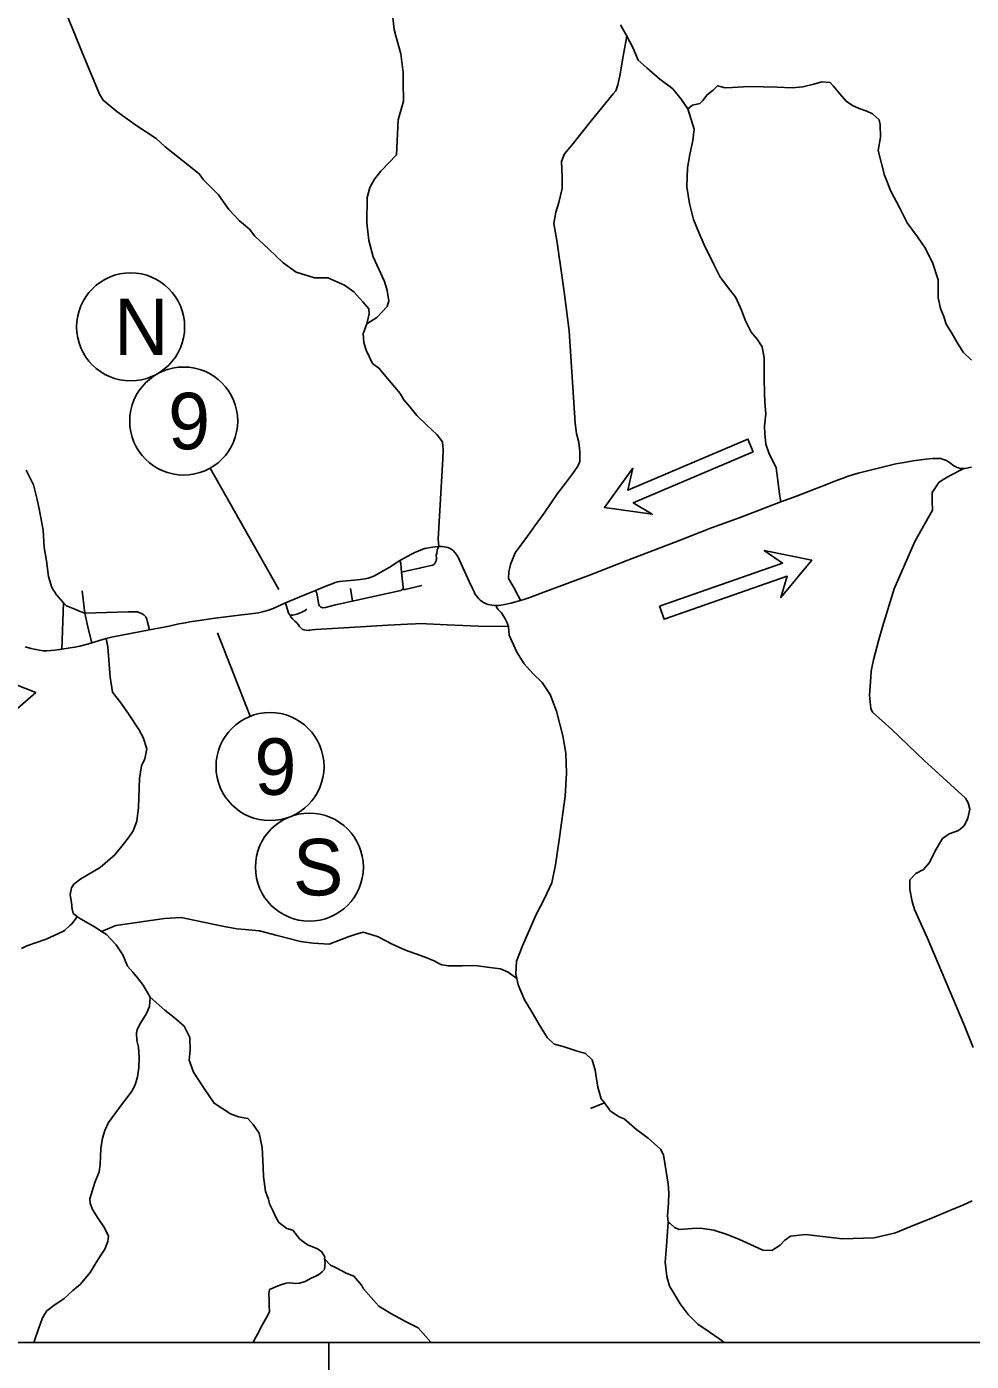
# Model space of a CAD drawing. Extents: x 2025369 to 2161369, y 549489 to 637489.
# Drawn here: x 2069680 to 2081050, y 571334 to 587393 of the extents above; entities that cross this region are included whole.
import ezdxf

# ---------------------------------------------------------------- set-up
doc = ezdxf.new("R2010")
doc.units = 0
for name, color, linetype in [('GM_X_County_Road', 7, 'Continuous'), ('GM_X_State_Route', 7, 'Continuous'), ('GM_X_Township_Road', 7, 'Continuous'), ('GM_X_Township_Subdivision', 7, 'Continuous'), ('SH_Text', 7, 'Continuous')]:
    doc.layers.add(name, color=color, linetype=linetype)

msp = doc.modelspace()

# ---------------------------------------------------------------- linework, layer by layer
at = {"layer": 'GM_X_County_Road'}
for points in [[(2074211, 586792), (2074210, 586841), (2074183, 587067), (2074128, 587266), (2074102, 587360), (2074085, 587539)], [(2078759, 581674), (2078741, 581768), (2078720, 581933), (2078703, 582084), (2078613, 582264), (2078576, 582370), (2078564, 582499), (2078561, 582585), (2078577, 582735), (2078566, 582873), (2078559, 582986), (2078555, 583154), (2078557, 583408), (2078533, 583541), (2078471, 583633), (2078402, 583716), (2078330, 583852), (2078283, 583981), (2078216, 584135), (2078116, 584262), (2078021, 584389), (2077951, 584531), (2077834, 584770), (2077769, 584915), (2077706, 585073), (2077658, 585266), (2077627, 585466), (2077632, 585693), (2077661, 585855), (2077698, 586023), (2077713, 586161), (2077636, 586406), (2077556, 586521), (2077457, 586646), (2077301, 586760), (2077146, 586897), (2077040, 586992), (2076977, 587142), (2076905, 587280), (2076826, 587416)], [(2073755, 583767), (2073775, 583816), (2073893, 583895), (2074020, 584027), (2074040, 584094), (2074020, 584217), (2073988, 584326), (2073850, 584625), (2073797, 584820), (2073775, 585034), (2073779, 585338), (2073811, 585460), (2073865, 585560), (2073942, 585655), (2074133, 585850), (2074151, 586274), (2074214, 586496), (2074211, 586731), (2074211, 586792)], [(2074296, 582814), (2074268, 582848), (2074218, 582904), (2074174, 582979), (2073919, 583286), (2073843, 583342), (2073765, 583500), (2073738, 583591), (2073728, 583700), (2073746, 583743), (2073755, 583767)], [(2074640, 581137), (2074634, 581227), (2074689, 582195), (2074692, 582301), (2074686, 582397), (2074616, 582484), (2074495, 582599), (2074377, 582715), (2074311, 582796), (2074296, 582814)], [(2078074, 571561), (2078025, 571602), (2077895, 571689), (2077760, 571779), (2077640, 571896), (2077547, 572025), (2077456, 572175), (2077418, 572238), (2077384, 572356), (2077365, 572526), (2077382, 572721), (2077401, 573009), (2077393, 573085), (2077404, 573242), (2077411, 573358), (2077401, 573466), (2077378, 573617), (2077345, 573819), (2077309, 573885), (2077162, 574020), (2077024, 574119), (2076870, 574252), (2076813, 574276), (2076709, 574345), (2076635, 574442), (2076595, 574494), (2076556, 574634), (2076540, 574734), (2076523, 574839), (2076487, 574963), (2076408, 575037), (2076292, 575070), (2076138, 575121), (2076028, 575149), (2075944, 575230), (2075849, 575388), (2075748, 575559), (2075672, 575682), (2075597, 575864), (2075578, 575942), (2075566, 575991), (2075576, 576147), (2075649, 576335), (2075716, 576489), (2075817, 576719), (2075914, 576901), (2076001, 577093), (2076044, 577308), (2076095, 577636), (2076162, 578133), (2076177, 578409), (2076168, 578650), (2076135, 578862), (2076058, 579157), (2075979, 579356), (2075886, 579503), (2075774, 579611), (2075669, 579726), (2075581, 579867), (2075488, 580072), (2075478, 580175), (2075461, 580228), (2075436, 580277), (2075397, 580340), (2075374, 580360), (2075355, 580379), (2075340, 580400), (2075329, 580427)], [(2069766, 571561), (2069782, 571610), (2069838, 571770), (2069874, 571866), (2069923, 571943), (2070005, 572005), (2070130, 572091), (2070237, 572185), (2070326, 572262), (2070444, 572404), (2070504, 572502), (2070566, 572600), (2070619, 572685), (2070657, 572776), (2070666, 572840), (2070615, 572938), (2070540, 573052), (2070471, 573162), (2070446, 573236), (2070441, 573290), (2070501, 573486), (2070553, 573615), (2070565, 573701), (2070571, 573895), (2070591, 574017), (2070620, 574110), (2070665, 574209), (2070752, 574328), (2070822, 574419), (2070890, 574509), (2070944, 574583), (2070984, 574662), (2071013, 574757), (2071029, 574864), (2071035, 574990), (2071024, 575115), (2071006, 575194), (2071000, 575282), (2071008, 575326), (2071049, 575401), (2071124, 575517), (2071158, 575603), (2071165, 575717), (2071081, 575859), (2071014, 575948), (2070957, 576015), (2070895, 576088), (2070837, 576226), (2070758, 576345), (2070642, 576469), (2070581, 576507), (2070516, 576548), (2070391, 576621), (2070308, 576670), (2070289, 576685), (2070240, 576723), (2070227, 576773), (2070218, 576851), (2070205, 576950), (2070220, 577031), (2070248, 577077), (2070331, 577138), (2070448, 577208), (2070565, 577277), (2070741, 577427), (2070842, 577551), (2070901, 577627), (2070962, 577716), (2071007, 577833), (2071025, 577997), (2071039, 578345), (2071063, 578500), (2071100, 578584), (2071125, 578703), (2071083, 578838), (2071030, 578936), (2070912, 579112), (2070815, 579257), (2070754, 579334), (2070711, 579386), (2070683, 579566), (2070656, 579930), (2070635, 580030)]]:
    msp.add_lwpolyline(points, dxfattribs=at)
at = {"layer": 'GM_X_State_Route'}
for points in [[(2075329, 580427), (2075359, 580429), (2075391, 580434), (2075435, 580442), (2075508, 580457), (2075625, 580489), (2075677, 580504), (2075735, 580523), (2075871, 580575), (2076465, 580799), (2076914, 580972), (2077525, 581205), (2077923, 581361), (2078266, 581489), (2078759, 581674), (2078945, 581745), (2079307, 581884), (2079427, 581931), (2079506, 581960), (2079557, 581979), (2079618, 581999), (2079687, 582019), (2079799, 582050), (2080012, 582102), (2080140, 582131), (2080241, 582151), (2080348, 582169), (2080413, 582178), (2080501, 582189), (2080582, 582197), (2080632, 582199), (2080663, 582198), (2080683, 582196), (2080705, 582191), (2080729, 582182), (2080750, 582172), (2080788, 582149), (2080841, 582110), (2080862, 582097), (2080879, 582089), (2080895, 582083), (2080915, 582077), (2080932, 582075), (2080946, 582075), (2080960, 582075), (2080977, 582078), (2080997, 582082), (2081029, 582088), (2081053, 582091)], [(2069661, 579932), (2069732, 579912), (2069768, 579903), (2069793, 579897), (2069831, 579889), (2069882, 579884), (2069923, 579883), (2069971, 579885), (2070018, 579889), (2070102, 579901), (2070202, 579917), (2070261, 579926), (2070320, 579938), (2070396, 579958), (2070463, 579978), (2070635, 580030), (2070683, 580042), (2070722, 580051), (2071158, 580134), (2071394, 580181), (2071513, 580206), (2071592, 580221), (2071644, 580231), (2071705, 580241), (2071790, 580253), (2071918, 580271), (2072271, 580315), (2072340, 580323), (2072406, 580332), (2072470, 580342), (2072535, 580356), (2072590, 580371), (2072647, 580391), (2072794, 580462), (2073077, 580577), (2073158, 580609), (2073222, 580635), (2073311, 580672), (2073358, 580690), (2073393, 580704), (2073422, 580712), (2073449, 580718), (2073486, 580723), (2073623, 580734), (2073692, 580740), (2073721, 580744), (2073754, 580750), (2073789, 580757), (2073828, 580770), (2073865, 580786), (2073942, 580828), (2074041, 580886), (2074173, 580971), (2074267, 581023), (2074304, 581043), (2074361, 581071), (2074390, 581083), (2074421, 581096), (2074449, 581107), (2074474, 581113), (2074498, 581119), (2074541, 581128), (2074595, 581133), (2074640, 581137)], [(2074640, 581137), (2074680, 581137), (2074704, 581135), (2074727, 581132), (2074748, 581127), (2074768, 581119), (2074790, 581107), (2074812, 581092), (2074835, 581068), (2074849, 581048), (2074873, 581008), (2074926, 580893), (2075005, 580716), (2075046, 580631), (2075065, 580593), (2075076, 580570), (2075089, 580549), (2075102, 580531), (2075121, 580510), (2075139, 580493), (2075166, 580473), (2075187, 580461), (2075211, 580450), (2075235, 580441), (2075279, 580431), (2075305, 580427), (2075329, 580427)]]:
    msp.add_lwpolyline(points, dxfattribs=at)
at = {"layer": 'GM_X_Township_Road'}
for points in [[(2073775, 583816), (2073801, 583938), (2073798, 583998), (2073727, 584084), (2073616, 584204), (2073507, 584281), (2073306, 584371), (2073145, 584373), (2072922, 584440), (2072767, 584550), (2072591, 584720), (2072427, 584874), (2072361, 584957), (2072243, 585058), (2072112, 585194), (2071988, 585371), (2071810, 585549), (2071757, 585624), (2071501, 585829), (2071346, 585949), (2071237, 586046), (2070993, 586209), (2070766, 586371), (2070602, 586507), (2070556, 586582), (2070338, 587102), (2070256, 587313), (2070171, 587514)], [(2076094, 584593), (2076066, 584795), (2076025, 585026), (2076051, 585160), (2076086, 585278), (2076127, 585444), (2076127, 585588), (2076116, 585771), (2076152, 585863), (2076243, 585967), (2076476, 586259), (2076738, 586584), (2076770, 586622), (2076796, 586694), (2076819, 586800), (2076860, 587037), (2076905, 587280)], [(2081052, 583381), (2080952, 583475), (2080878, 583592), (2080817, 583706), (2080749, 583815), (2080718, 583905), (2080680, 584001), (2080651, 584132), (2080650, 584348), (2080581, 584557), (2080491, 584738), (2080404, 584866), (2080279, 585033), (2080185, 585218), (2080080, 585413), (2080005, 585605), (2079930, 585902), (2079957, 586065), (2079952, 586217), (2079940, 586271), (2079860, 586343), (2079792, 586376), (2079701, 586408), (2079621, 586443), (2079545, 586497), (2079469, 586586), (2079388, 586682), (2079350, 586720), (2079252, 586731), (2079154, 586703), (2079023, 586669), (2078893, 586658), (2078713, 586665), (2078375, 586674), (2078175, 586661), (2078087, 586657), (2077995, 586683), (2077941, 586628), (2077872, 586572), (2077818, 586504), (2077784, 586470), (2077692, 586450), (2077636, 586406)], [(2075843, 581450), (2075917, 581553), (2076070, 581777), (2076165, 581901), (2076249, 582013), (2076314, 582105), (2076336, 582163), (2076338, 582281), (2076327, 582391), (2076299, 582497), (2076282, 582624), (2076209, 583732), (2076149, 584204), (2076097, 584573), (2076094, 584593)], [(2070325, 580357), (2070260, 580383), (2070158, 580423), (2070124, 580461), (2070038, 580555), (2069981, 580646), (2069941, 580778), (2069920, 580967), (2069892, 581127), (2069878, 581335), (2069831, 581590), (2069803, 581720), (2069762, 581880), (2069672, 582057)], [(2081072, 575109), (2080958, 575390), (2080518, 576432), (2080367, 576770), (2080340, 576868), (2080309, 577012), (2080309, 577127), (2080381, 577204), (2080476, 577252), (2080546, 577336), (2080613, 577478), (2080703, 577624), (2080784, 577680), (2080896, 577721), (2080962, 577777), (2081009, 577871), (2081033, 577979), (2081012, 578054), (2080980, 578108), (2080484, 578563), (2080093, 578935), (2079862, 579146), (2079840, 579189), (2079823, 579351), (2079840, 579567), (2079845, 579640), (2079862, 579719), (2079871, 579773), (2079933, 580004), (2079981, 580170), (2080121, 580629), (2080369, 581197), (2080583, 581577), (2080580, 581681), (2080578, 581789), (2080659, 581910), (2080698, 581938), (2080794, 581991), (2080960, 582075)], [(2075625, 580489), (2075608, 580525), (2075583, 580564), (2075559, 580615), (2075479, 580755), (2075483, 580835), (2075502, 580921), (2075561, 581061), (2075709, 581263), (2075818, 581415), (2075843, 581450)], [(2070463, 579978), (2070427, 580119), (2070407, 580209), (2070379, 580336), (2070325, 580357)], [(2069617, 576302), (2069681, 576334), (2069916, 576415), (2070114, 576505), (2070135, 576518), (2070203, 576580), (2070224, 576598), (2070241, 576618), (2070273, 576661), (2070289, 576685)], [(2070581, 576507), (2070754, 576576), (2071339, 576663), (2071541, 576673), (2072038, 576571), (2072208, 576539), (2072309, 576529), (2072481, 576512), (2072696, 576459), (2072976, 576387), (2073127, 576367), (2073320, 576352), (2073549, 576442), (2073634, 576470), (2073730, 576496), (2073901, 576446), (2074079, 576352), (2074238, 576280), (2074476, 576195), (2074594, 576147), (2074642, 576121), (2074678, 576106), (2074758, 576094), (2074924, 576091), (2075078, 576095), (2075224, 576076), (2075384, 576056), (2075474, 576017), (2075578, 575942)], [(2074546, 571561), (2074544, 571565), (2074393, 571735), (2074241, 571811), (2074072, 571905), (2073920, 571999), (2073732, 572207), (2073713, 572245), (2073618, 572358), (2073524, 572396), (2073411, 572453), (2073335, 572490), (2073263, 572567), (2073268, 572592), (2073228, 572655), (2073171, 572690), (2073059, 572735), (2072968, 572802), (2072885, 572911), (2072813, 572930), (2072714, 573003), (2072677, 573069), (2072641, 573150), (2072604, 573228), (2072589, 573284), (2072556, 573379), (2072532, 573557), (2072525, 573669), (2072514, 573907), (2072480, 574077), (2072407, 574184), (2072342, 574255), (2072230, 574276), (2072134, 574313), (2071936, 574438), (2071815, 574617), (2071686, 574813), (2071635, 574957), (2071649, 575079), (2071642, 575229), (2071576, 575366), (2071455, 575469), (2071344, 575560), (2071165, 575717)], [(2076635, 574442), (2076465, 574376)], [(2077401, 573009), (2077423, 572995), (2077477, 572943), (2077533, 572921), (2077689, 572930), (2077791, 572936), (2077949, 572913), (2078111, 572860), (2078259, 572801), (2078394, 572739), (2078540, 572672), (2078648, 572666), (2078748, 572731), (2078805, 572793), (2078873, 572839), (2079055, 572861), (2079501, 572809), (2079879, 572821), (2080138, 572878), (2080320, 572954), (2080611, 573071), (2080793, 573148), (2080946, 573214), (2081062, 573265)], [(2072407, 571561), (2072416, 571589), (2072458, 571659), (2072520, 571776), (2072583, 571891), (2072604, 571935), (2072600, 572007), (2072597, 572075), (2072596, 572143), (2072603, 572197), (2072685, 572232), (2072739, 572255), (2072802, 572274), (2072848, 572280), (2072918, 572271), (2072962, 572274), (2073032, 572296), (2073103, 572333), (2073159, 572360), (2073207, 572387), (2073236, 572411), (2073264, 572439), (2073271, 572522), (2073263, 572567)]]:
    msp.add_lwpolyline(points, dxfattribs=at)
at = {"layer": 'GM_X_Township_Subdivision'}
for points in [[(2074193, 580830), (2074228, 580839), (2074297, 580853), (2074372, 580871), (2074476, 580893), (2074547, 580908), (2074567, 580915), (2074586, 580926), (2074598, 580941), (2074609, 580965), (2074611, 580993), (2074610, 581033), (2074615, 581055), (2074622, 581098), (2074628, 581113), (2074640, 581137)], [(2074173, 580971), (2074183, 580932), (2074193, 580830), (2074212, 580645), (2074210, 580632), (2074206, 580625)], [(2070379, 580336), (2070347, 580606)], [(2073158, 580609), (2073172, 580577), (2073183, 580509), (2073193, 580456), (2073198, 580438), (2073206, 580424), (2073222, 580409), (2073246, 580401), (2073277, 580404), (2073398, 580435), (2073603, 580481), (2073654, 580491), (2074185, 580608), (2074198, 580615), (2074206, 580625), (2074219, 580621), (2074234, 580621), (2074252, 580625)], [(2073603, 580481), (2073576, 580632)], [(2074252, 580625), (2074435, 580667)], [(2070102, 579901), (2070124, 580461)], [(2072794, 580462), (2072833, 580337), (2072848, 580316), (2072862, 580310), (2072882, 580312), (2072931, 580325), (2072982, 580344), (2073032, 580368), (2073050, 580383)], [(2070379, 580336), (2070903, 580351)], [(2070903, 580351), (2071011, 580354), (2071040, 580342), (2071068, 580330), (2071090, 580317), (2071114, 580291), (2071125, 580263), (2071133, 580228), (2071158, 580134)], [(2072848, 580316), (2072860, 580293), (2072879, 580266), (2072907, 580238), (2072930, 580218), (2072951, 580196), (2072964, 580175), (2072981, 580158), (2072996, 580145), (2073014, 580137), (2073038, 580132), (2073076, 580129), (2073085, 580130)], [(2073085, 580130), (2073116, 580134), (2073157, 580138), (2073564, 580162), (2074027, 580193), (2074262, 580205), (2074361, 580209)], [(2074361, 580209), (2074407, 580211), (2074743, 580197), (2075119, 580181), (2075478, 580175)]]:
    msp.add_lwpolyline(points, dxfattribs=at)
at = {"layer": 'SH_Text'}
for p, q in [((2072713, 580619), (2071889, 582082)), ((2071977, 580101), (2072371, 579096)), ((2073318, 571561), (2073318, 564989))]:
    msp.add_line(p, q, dxfattribs=at)
msp.add_lwpolyline([(2037369, 631489), (2037369, 571561), (2092420, 571561), (2092420, 631489)], dxfattribs=at)
for points in [[(2078426, 582277), (2078361, 582431), (2076915, 581818), (2076976, 582079), (2076633, 581608), (2077210, 581527), (2076980, 581665)], [(2077297, 580419), (2077352, 580262), (2078834, 580781), (2078756, 580524), (2079129, 580973), (2078558, 581091), (2078779, 580938)], [(2067890, 579143), (2067918, 578979), (2069466, 579243), (2069347, 579002), (2069789, 579382), (2069246, 579594), (2069439, 579407)]]:
    msp.add_lwpolyline(points, close=True, dxfattribs=at)
for centre in [(2070931, 583781), (2071570, 582648), (2072609, 578490), (2073083, 577280)]:
    msp.add_circle(centre, 650, dxfattribs=at)

# ---------------------------------------------------------------- texts
for s, p in [('N', (2070731, 583441)), ('9', (2071382, 582308)), ('9', (2072421, 578150)), ('S', (2072885, 576940))]:
    msp.add_text(s, height=680, dxfattribs=at).set_placement(p)

doc.saveas('drawing.dxf')
